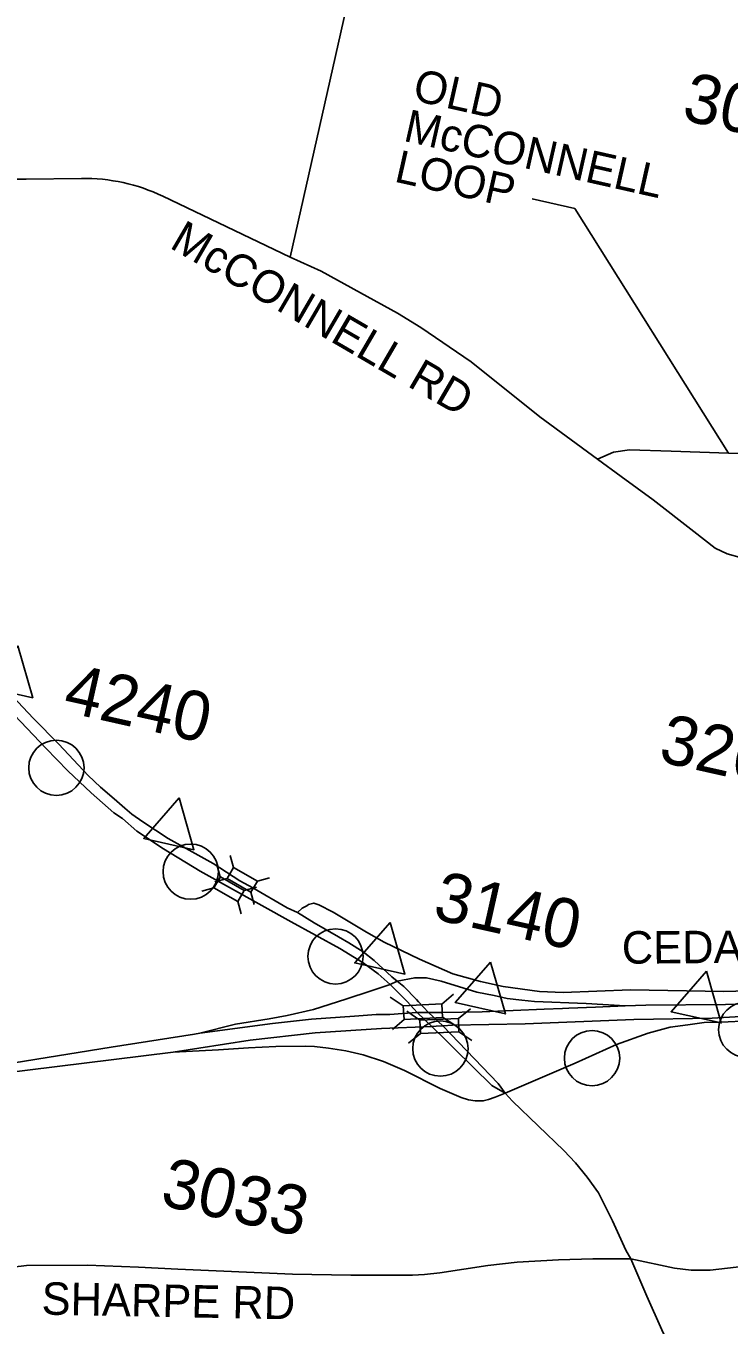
# Model space of a CAD drawing. Extents: x 1784499 to 1786147, y 841097 to 842538.
# Drawn here: x 1784672 to 1784767.1, y 842146.6 to 842322.5 of the extents above; entities that cross this region are included whole.
import ezdxf

# ---------------------------------------------------------------- set-up
doc = ezdxf.new("R2010")
doc.units = 0
for name, color, linetype in [('DEV CONE PLAN VIEW CELL', 7, 'Continuous'), ('Exist Road Primary Interstate Divided Center Attributed', 7, 'Continuous'), ('Exist Road Primary Interstate Ramp 1 Lane Attributed', 7, 'Continuous'), ('Exist Road Primary Interstate Structure Standard Bridge CELL', 7, 'Continuous'), ('Exist Road Primary NC Divided Attributed', 7, 'Continuous'), ('Exist Road Secondary Structure Standard Bridge CELL', 7, 'Continuous'), ('Exist Road Secondary Type 51 Attributed', 7, 'Continuous'), ('Exist Road Secondary Type 51 Divided Attributed', 7, 'Continuous'), ('Exist Road Secondary Type 51 Number Label', 7, 'Continuous'), ('Old_Level_1', 7, 'Continuous'), ('Prop DSN Text', 7, 'Continuous'), ('Scratch_Level_3', 7, 'Continuous')]:
    doc.layers.add(name, color=color, linetype=linetype)

msp = doc.modelspace()

# ---------------------------------------------------------------- linework, layer by layer
at = {"layer": 'DEV CONE PLAN VIEW CELL'}
for points in [[(1784670.88, 842238.55), (1784666.09, 842233.07), (1784672.89, 842231.54)], [(1784692.7, 842217.97), (1784687.9, 842212.48), (1784694.7, 842210.96)], [(1784721.25, 842201.12), (1784716.45, 842195.63), (1784723.25, 842194.11)], [(1784734.84, 842195.74), (1784730.04, 842190.26), (1784736.84, 842188.73)], [(1784764.05, 842194.51), (1784759.25, 842189.02), (1784766.05, 842187.5)]]:
    msp.add_lwpolyline(points, close=True, dxfattribs=at)
for centre in [(1784676.08, 842222.05), (1784694.26, 842207.99), (1784713.85, 842196.51), (1784769.42, 842186.58), (1784728.04, 842184.03), (1784748.56, 842182.74)]:
    msp.add_circle(centre, 3.74, dxfattribs=at)
at = {"layer": 'Exist Road Primary Interstate Divided Center Attributed'}
for points in [[(1784892.4, 842193.99), (1784887.07, 842193.79), (1784881.29, 842193.62), (1784873.67, 842193.29), (1784867.2, 842193.21), (1784859.72, 842193.02), (1784844.96, 842192.54), (1784839.42, 842192.34), (1784830.45, 842192.32), (1784816.61, 842191.67), (1784810.04, 842191.4), (1784802.34, 842191.25), (1784791.56, 842190.92), (1784785.16, 842190.77), (1784776.81, 842190.33), (1784766.61, 842190.01), (1784755.84, 842189.9), (1784753.05, 842189.8)], [(1784724.9, 842188.92), (1784722.91, 842188.79), (1784721.22, 842188.66), (1784719.33, 842188.65), (1784716.4, 842188.44), (1784710.59, 842188.01), (1784705.34, 842187.45), (1784695.5, 842186.11)], [(1784726.42, 842188.91), (1784725.65, 842188.92), (1784724.9, 842188.92)], [(1784753.05, 842189.8), (1784749.04, 842189.64), (1784745.44, 842189.51), (1784744.58, 842189.46), (1784742.08, 842189.35), (1784733.68, 842189.01), (1784728.23, 842188.93), (1784726.42, 842188.91)], [(1784532.85, 842186.86), (1784537.05, 842186.1), (1784563.83, 842180.98), (1784574.03, 842179.03), (1784603.58, 842174.08), (1784610.49, 842173.51), (1784613.69, 842173.48), (1784620.87, 842173.82), (1784631.94, 842175.24), (1784637.58, 842176.2), (1784644.35, 842177.19), (1784654.07, 842178.21), (1784668.12, 842180.62), (1784691.88, 842183.53)], [(1784691.88, 842183.53), (1784702.29, 842185.17), (1784711.11, 842186.15), (1784720.06, 842186.75), (1784726.88, 842187.02)], [(1784726.88, 842187.02), (1784727.48, 842187.08), (1784728.39, 842187.12)], [(1784728.39, 842187.12), (1784729.7, 842187.19), (1784739.5, 842187.38), (1784754.22, 842187.95), (1784764.82, 842188.17), (1784768.7, 842188.39), (1784774.51, 842188.49)], [(1784695.5, 842186.11), (1784694.75, 842185.99), (1784683.49, 842184.23), (1784670.39, 842182.1), (1784654.76, 842179.82), (1784638.8, 842177.48), (1784632.47, 842176.57), (1784622.77, 842175.18), (1784617.69, 842174.87), (1784614.95, 842174.59), (1784611.84, 842174.62), (1784607.96, 842174.71), (1784604.36, 842175.07), (1784599.81, 842175.9), (1784594.13, 842176.92), (1784589.92, 842177.64), (1784586.2, 842178.48), (1784570.37, 842181.25), (1784566.24, 842182.17), (1784565.29, 842182.34)]]:
    msp.add_lwpolyline(points, dxfattribs=at)
at = {"layer": 'Exist Road Primary Interstate Ramp 1 Lane Attributed'}
for points in [[(1784721.25, 842192.7), (1784718.67, 842191.83), (1784715.25, 842190.72), (1784710.88, 842189.31), (1784707.31, 842188.53), (1784704.89, 842188.06), (1784700.33, 842187.34), (1784695.5, 842186.11)], [(1784722.17, 842193.18), (1784721.25, 842192.7)], [(1784753.05, 842189.8), (1784747.77, 842190.12), (1784740.76, 842190.42), (1784739.06, 842190.59), (1784737.09, 842190.81), (1784735.3, 842191.21), (1784732.95, 842191.67), (1784728.15, 842193.18), (1784726.16, 842193.63), (1784724.57, 842193.62), (1784722.17, 842193.18)], [(1784736.82, 842178), (1784746.26, 842182.07), (1784751.88, 842184.57), (1784756.13, 842186.14), (1784759.12, 842186.92), (1784761.51, 842187.25), (1784763.74, 842187.55), (1784766.07, 842187.6), (1784769.73, 842187.8), (1784774.51, 842188.49)], [(1784691.88, 842183.53), (1784698.03, 842183.88), (1784702.06, 842184.13), (1784705.79, 842184.31), (1784709.77, 842184.36), (1784710.99, 842184.3), (1784712.89, 842184.09), (1784715.26, 842183.71), (1784717.6, 842183.18), (1784720.36, 842182.27), (1784723.2, 842181.06), (1784727.99, 842178.61), (1784730.83, 842177.39), (1784731.85, 842177.09), (1784732.76, 842176.96), (1784733.83, 842176.94), (1784734.53, 842177.14), (1784735.46, 842177.44), (1784736.82, 842178)]]:
    msp.add_lwpolyline(points, dxfattribs=at)
at = {"layer": 'Exist Road Primary Interstate Structure Standard Bridge CELL'}
for p, q in [((1784721.25, 842190.98), (1784723.02, 842189.8)), ((1784728.22, 842190.06), (1784729.82, 842191.41)), ((1784723.52, 842189.1), (1784725.26, 842187.9)), ((1784730.47, 842188.1), (1784732.1, 842189.42)), ((1784721.54, 842186.63), (1784723.14, 842187.98)), ((1784728.34, 842188.28), (1784730.11, 842187.11)), ((1784723.71, 842184.75), (1784725.34, 842186.08)), ((1784730.55, 842186.31), (1784732.29, 842185.12))]:
    msp.add_line(p, q, dxfattribs=at)
for points in [[(1784723.02, 842189.8), (1784728.22, 842190.07), (1784728.34, 842188.25), (1784723.14, 842187.98)], [(1784725.26, 842187.9), (1784730.47, 842188.11), (1784730.55, 842186.28), (1784725.34, 842186.08)]]:
    msp.add_lwpolyline(points, close=True, dxfattribs=at)
at = {"layer": 'Exist Road Primary NC Divided Attributed'}
for p, q in [((1784724.9, 842188.92), (1784726.88, 842187.02)), ((1784728.39, 842187.12), (1784726.42, 842188.91))]:
    msp.add_line(p, q, dxfattribs=at)
at = {"layer": 'Exist Road Secondary Structure Standard Bridge CELL'}
for p, q in [((1784700.03, 842208.53), (1784699.59, 842210.17)), ((1784698.25, 842207.27), (1784697.81, 842208.92)), ((1784699.18, 842207.05), (1784697.54, 842206.61)), ((1784704.92, 842207.14), (1784703.28, 842206.7)), ((1784697.4, 842205.8), (1784695.76, 842205.35)), ((1784703.14, 842205.88), (1784701.5, 842205.44)), ((1784702.85, 842203.54), (1784702.41, 842205.19)), ((1784701.07, 842202.29), (1784700.63, 842203.93))]:
    msp.add_line(p, q, dxfattribs=at)
for points in [[(1784702.41, 842205.19), (1784699.18, 842207.05), (1784700.05, 842208.56), (1784703.28, 842206.7)], [(1784700.63, 842203.93), (1784697.4, 842205.79), (1784698.27, 842207.3), (1784701.5, 842205.44)]]:
    msp.add_lwpolyline(points, close=True, dxfattribs=at)
at = {"layer": 'Exist Road Secondary Type 51 Attributed'}
for p, q in [((1784722.62, 842357.35), (1784707.72, 842291.21)), ((1784671.97, 842301.76), (1784679.47, 842301.86)), ((1784690.48, 842299.44), (1784707.72, 842291.21))]:
    msp.add_line(p, q, dxfattribs=at)
for points in [[(1784749.29, 842263.86), (1784741.5, 842269.56), (1784732.2, 842277), (1784725.39, 842281.65), (1784722.22, 842283.6), (1784717.22, 842286.34), (1784711.9, 842289.28), (1784707.72, 842291.21)], [(1784749.29, 842263.86), (1784751.48, 842264.77), (1784753.64, 842265.08), (1784759.28, 842264.91), (1784767, 842264.67), (1784775.93, 842264.5)], [(1784794.94, 842243.56), (1784791.78, 842244.55), (1784786.93, 842245.7), (1784783.91, 842246.47), (1784776.37, 842248.16), (1784768.77, 842250.47), (1784766.86, 842251), (1784765.2, 842251.78), (1784762.35, 842254.04), (1784756.81, 842258.33), (1784752.52, 842261.5), (1784749.29, 842263.86)], [(1784736.82, 842178), (1784737.8, 842176.92), (1784744.76, 842170.22), (1784746.34, 842168.57), (1784747.92, 842166.62), (1784749.41, 842164.5), (1784751.33, 842160.73), (1784753.15, 842156.74), (1784753.8, 842155.56)], [(1784753.8, 842155.56), (1784748.67, 842155.57), (1784744.03, 842155.43), (1784738.44, 842155.11), (1784734.44, 842154.67), (1784727.95, 842153.66), (1784725.9, 842153.43), (1784724.28, 842153.35), (1784715.91, 842153.37), (1784708.01, 842153.5), (1784692.53, 842154.16), (1784687.21, 842154.42), (1784680.28, 842154.71), (1784672.03, 842154.64), (1784665.73, 842153.9), (1784657.5, 842152.49), (1784647.14, 842150.27), (1784642.12, 842149.02), (1784640.81, 842148.57)], [(1784753.8, 842155.56), (1784755.99, 842150.5), (1784757.99, 842145.97), (1784759.68, 842142.46)], [(1784780, 842150.37), (1784777.8, 842152.27), (1784775.22, 842153.83), (1784773.25, 842154.41), (1784771.32, 842154.57), (1784769.22, 842154.55), (1784764.56, 842154.05), (1784761.96, 842154.01), (1784759.71, 842154.3), (1784753.8, 842155.56)]]:
    msp.add_lwpolyline(points, dxfattribs=at)
for centre, radius, start, end in [((1784670.55, 842414.49), 112.74, 265.0175, 270.724), ((1784679.79, 842277.03), 24.83, 64.4933, 90.724)]:
    msp.add_arc(centre, radius, start, end, dxfattribs=at)
at = {"layer": 'Exist Road Secondary Type 51 Divided Attributed'}
msp.add_line((1784707.83, 842201.18), (1784699.5, 842205.85), dxfattribs=at)
for points in [[(1784699.5, 842205.85), (1784695.55, 842208.04), (1784690.56, 842211.06), (1784686.96, 842213.47), (1784685.01, 842215.18), (1784683.87, 842215.95), (1784680.77, 842218.66), (1784677.62, 842221.62), (1784674.65, 842224.7), (1784667, 842232.72)], [(1784700.89, 842206.73), (1784697.28, 842209.09), (1784691.22, 842212.46), (1784687.78, 842214.72), (1784686.31, 842215.79), (1784685.35, 842216.6), (1784683.92, 842217.84), (1784682.05, 842219.43), (1784680.36, 842221), (1784676.4, 842225.26), (1784673, 842228.71), (1784667.96, 842233.99)], [(1784708.72, 842202.44), (1784707.29, 842203.08), (1784702.66, 842205.8), (1784700.89, 842206.73)], [(1784707.83, 842201.18), (1784714.45, 842197.57), (1784717.57, 842195.66), (1784719.61, 842194.15), (1784721.25, 842192.7)], [(1784722.17, 842193.18), (1784721.46, 842193.75), (1784719.06, 842195.97), (1784717.57, 842197.15), (1784715.67, 842198.37), (1784714.24, 842199.17), (1784710.96, 842201.07), (1784708.72, 842202.44)], [(1784721.25, 842192.7), (1784723.09, 842190.87), (1784723.53, 842190.39), (1784724.9, 842188.92)], [(1784726.42, 842188.91), (1784725.09, 842190.36), (1784724.8, 842190.69), (1784723.08, 842192.45), (1784722.17, 842193.18)], [(1784726.88, 842187.02), (1784728.85, 842185.06), (1784729.93, 842184), (1784735.01, 842179.05), (1784736.82, 842178)], [(1784736.82, 842178), (1784735.86, 842179.31), (1784728.39, 842187.12)]]:
    msp.add_lwpolyline(points, dxfattribs=at)
at = {"layer": 'Old_Level_1'}
for points in [[(1784667, 842232.72), (1784674.65, 842224.7), (1784677.62, 842221.62), (1784680.77, 842218.66), (1784683.87, 842215.95), (1784685.01, 842215.18), (1784686.96, 842213.47), (1784690.56, 842211.06), (1784695.55, 842208.04), (1784699.5, 842205.85), (1784707.83, 842201.18)], [(1784708.72, 842202.44), (1784707.29, 842203.08), (1784702.66, 842205.8), (1784700.89, 842206.73), (1784697.28, 842209.09), (1784691.22, 842212.46), (1784687.78, 842214.72), (1784686.31, 842215.79), (1784685.35, 842216.6), (1784683.92, 842217.84), (1784682.05, 842219.43), (1784680.36, 842221), (1784676.4, 842225.26), (1784673, 842228.71), (1784667.96, 842233.99)], [(1784707.83, 842201.18), (1784714.45, 842197.57), (1784717.57, 842195.66), (1784719.61, 842194.15), (1784721.25, 842192.7)], [(1784722.17, 842193.18), (1784721.46, 842193.75), (1784719.06, 842195.97), (1784717.57, 842197.15), (1784715.67, 842198.37), (1784714.24, 842199.17), (1784710.96, 842201.07), (1784708.72, 842202.44)], [(1784721.25, 842192.7), (1784723.09, 842190.87), (1784723.53, 842190.39), (1784724.9, 842188.92)], [(1784726.42, 842188.91), (1784725.09, 842190.36), (1784724.8, 842190.69), (1784723.08, 842192.45), (1784722.17, 842193.18)], [(1784726.88, 842187.02), (1784728.85, 842185.06), (1784729.93, 842184), (1784735.01, 842179.05), (1784736.82, 842178)], [(1784736.82, 842178), (1784735.86, 842179.31), (1784728.39, 842187.12)], [(1784736.82, 842178), (1784737.8, 842176.92), (1784744.76, 842170.22), (1784746.34, 842168.57), (1784747.92, 842166.62), (1784749.41, 842164.5), (1784751.33, 842160.73), (1784753.15, 842156.74), (1784753.8, 842155.56)]]:
    msp.add_lwpolyline(points, dxfattribs=at)
at = {"layer": 'Prop DSN Text'}
for p, q in [((1784740.45, 842299.1), (1784746.25, 842297.79)), ((1784746.25, 842297.79), (1784767, 842264.67))]:
    msp.add_line(p, q, dxfattribs=at)
at = {"layer": 'Scratch_Level_3'}
msp.add_lwpolyline([(1784667.96, 842233.99), (1784673, 842228.71), (1784676.4, 842225.26), (1784680.36, 842221), (1784682.05, 842219.43), (1784683.92, 842217.84), (1784685.35, 842216.6), (1784686.31, 842215.79), (1784687.78, 842214.72), (1784691.22, 842212.46), (1784697.28, 842209.09), (1784700.89, 842206.73), (1784702.66, 842205.8), (1784707.29, 842203.08), (1784708.72, 842202.44), (1784709.35, 842203.05), (1784709.96, 842203.38), (1784710.18, 842203.54), (1784710.9, 842203.74), (1784711.57, 842203.49), (1784713.52, 842202.48), (1784718.05, 842199.81), (1784720.44, 842198.44), (1784725.23, 842196.12), (1784729.73, 842194.17), (1784733.45, 842193.12), (1784736.54, 842192.43), (1784741.44, 842191.75), (1784744.63, 842191.61), (1784753.75, 842191.98), (1784766.37, 842191.76), (1784771.29, 842191.91)], dxfattribs=at)

# ---------------------------------------------------------------- texts
at = {"layer": 'Exist Road Secondary Type 51 Number Label'}
for s, p in [('3008', (1784760.52, 842309.83)), ('4240', (1784676.8, 842229.71)), ('3267', (1784757.37, 842222.95)), ('3140', (1784726.82, 842201.64)), ('3033', (1784689.95, 842162.88))]:
    msp.add_text(s, height=6.665, rotation=347.3599, dxfattribs=at).set_placement(p)
at = {"layer": 'Prop DSN Text'}
for s, height, rotation, p in [('OLD ', 4.397, 347.336, (1784724.12, 842312.47)), ('McCONNELL ', 4.397, 347.336, (1784722.89, 842306.96)), ('LOOP', 4.397, 347.336, (1784721.65, 842301.45)), ('McCONNELL RD', 4.3971, 329.7826, (1784691.25, 842292.54)), ('CEDAR PARK RD', 4.3971, 0.3625, (1784752.6, 842195.52)), ('SHARPE RD', 4.397, 358.8982, (1784674.05, 842148.02))]:
    msp.add_text(s, height=height, rotation=rotation, dxfattribs=at).set_placement(p)

doc.saveas('drawing.dxf')
